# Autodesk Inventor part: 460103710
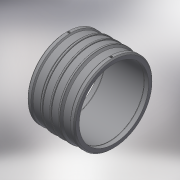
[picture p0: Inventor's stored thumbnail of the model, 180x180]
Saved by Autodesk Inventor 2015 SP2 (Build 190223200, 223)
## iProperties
Created: 2017-06
Part Number: 460103710
Material: Generic
Description: PLASSON LIGHTFIT COUPLER 710
Document SubType Name: Modeling
Designer: KIM
Mass: 46663.1 g
Surface Area: 25444.3 cm^2
Volume: 46663.1 cm^3
Density: 1 g/cm^3
Appearance: Default
Author: KIM
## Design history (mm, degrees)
derived "460103.ipt"
feature "Solid1::460103.ipt"
tag "TaggingFeature1"
body "Solid1"
other parameters: "d13" = 472, "d14" = 17.6296, "d15" = 236, "d16" = 236, "d19" = 3.52592, "d20" = 168 deg, "d23" = 817, "d24" = 776, "d25" = 135 deg, "d26" = 188.8, "d27" = 135 deg, "d35" = 15, "d39" = 0, "d40" = 4, "d41" = 14, "d42" = 0, "d43" = 135 deg, "d44" = 51.92, "d45" = 18.88, "d46" = 18.88, "d47" = 18.88, "d48" = 800.66, "d49" = 817, "d50" = 4.085, "d51" = 6, "d52" = 0, "L_" = 472, "L_1" = 236, "D_" = 817, "d_2" = 12
